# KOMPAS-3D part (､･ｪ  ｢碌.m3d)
File: created 29.01.2016 13:47:21, last saved 25.07.2016 11:16:17.
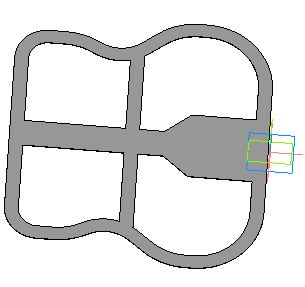
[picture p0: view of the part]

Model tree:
1. Эскиз:1
2. Операция выдавливания:1
     Толщина стенки 2 = 18; Расстояние 1 = 0.6
3. Эскиз:2
4. Вырезать элемент выдавливания:1
     Толщина стенки 2 = 2; Расстояние 1 = 30
5. Эскиз:3
6. Операция выдавливания:2
     Расстояние 1 = 0.6
7. Эскиз:4
8. Операция выдавливания:3
     Расстояние 1 = 0.6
